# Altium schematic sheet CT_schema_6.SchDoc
size 277 x 170 mm
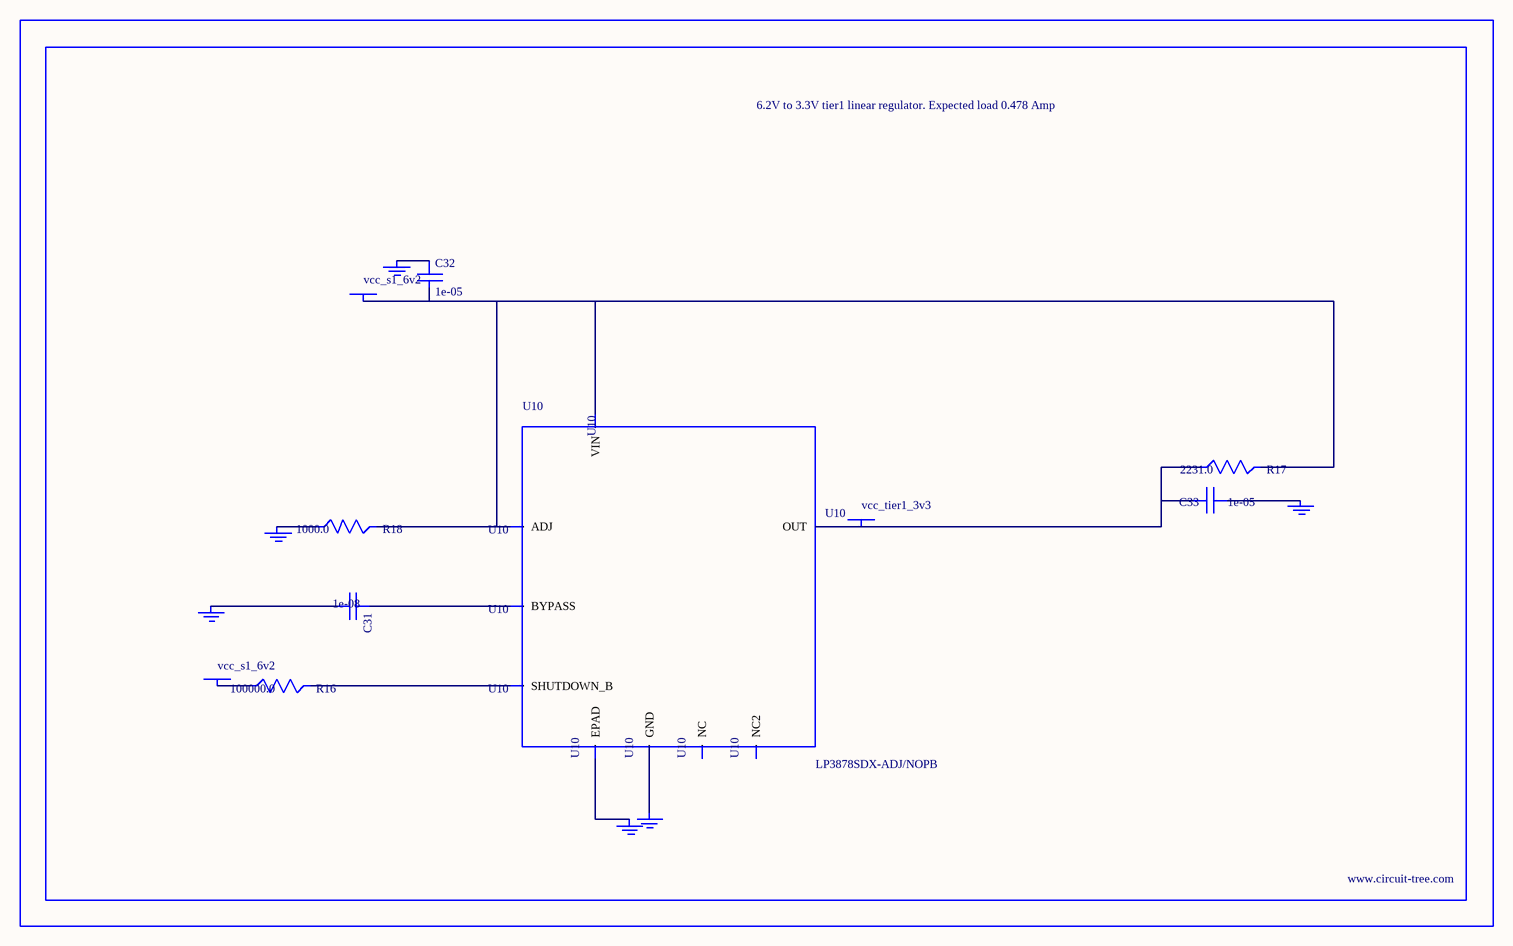
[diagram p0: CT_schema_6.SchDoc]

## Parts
BORDER5  (no value)
C31  1e-08  [C0402]
C32  1e-05  [C1206]
C33  1e-05  [C1210]
GND_INSTANCE_5_0  (no value)
GND_INSTANCE_5_1  (no value)
GND_INSTANCE_5_2  (no value)
GND_INSTANCE_5_3  (no value)
GND_INSTANCE_5_4  (no value)
GND_INSTANCE_5_5  (no value)
POWER_INSTANCE_5_0  vcc_s1_6v2
POWER_INSTANCE_5_1  vcc_s1_6v2
POWER_INSTANCE_5_2  vcc_tier1_3v3
R16  100000.0  [R0603]
R17  2231.0  [R0603]
R18  1000.0  [R0603]
U10  LP3878SDX-ADJ/NOPB  [WSON-8]

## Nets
NetC31_1: C31.1 U10.1(BYPASS)
NetC31_2: C31.2 GND_INSTANCE_5_0.0(GND)
NetC32_1: C32.1 GND_INSTANCE_5_1.0(GND)
NetC32_2: C32.2 POWER_INSTANCE_5_0.0(PWR) R17.2 R18.2 U10.4(VIN) U10.6(ADJ)
NetC33_1: C33.1 GND_INSTANCE_5_2.0(GND)
NetC33_2: C33.2 POWER_INSTANCE_5_2.0(PWR) R17.1 U10.5(OUT)
NetGND_INSTANCE_5_3_0: GND_INSTANCE_5_3.0(GND) R18.1
NetGND_INSTANCE_5_4_0: GND_INSTANCE_5_4.0(GND) U10.PAD(EPAD)
NetGND_INSTANCE_5_5_0: GND_INSTANCE_5_5.0(GND) U10.3(GND)
NetPOWER_INSTANCE_5_1_0: POWER_INSTANCE_5_1.0(PWR) R16.1
NetR16_2: R16.2 U10.8(SHUTDOWN_B)

Not connected (* = marked no-connect by the designer): U10 2(NC) 7(NC2)

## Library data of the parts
BORDER5 = BORDER_PAGE5
C31 = C0402C103K3RAC
C32 = C1206C106K3RACTU
C33 = GRM32DR61E106MA12L
GND_INSTANCE_5_0-GND_INSTANCE_5_5 = GND
POWER_INSTANCE_5_0-POWER_INSTANCE_5_2 = PWR
R16 = RC0603JR-07100KL
R17 = R17
R18 = RC0603JR-071KL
